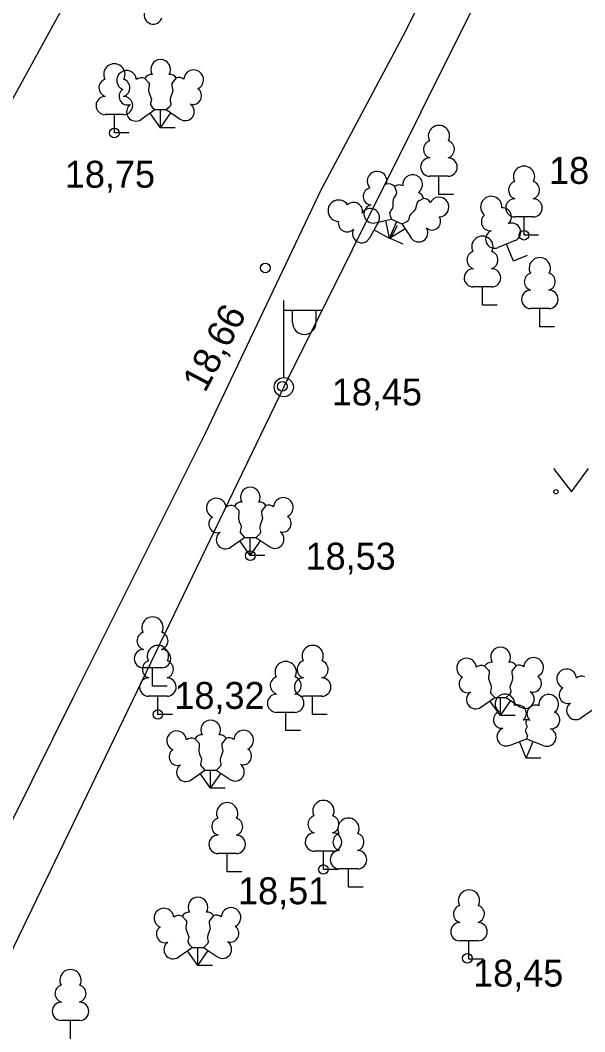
# Model space of a CAD drawing. Extents: x 713540 to 713867, y 6589774 to 6590061.
# Drawn here: x 713822.63 to 713837.3, y 6589948.37 to 6589974.67 of the extents above; entities that cross this region are included whole.
import ezdxf

# ---------------------------------------------------------------- set-up
doc = ezdxf.new("R2010")
doc.units = 0
for name, color, linetype in [('HALJASTUS', 7, 'Continuous'), ('HOONE', 7, 'Continuous'), ('KORGUS', 7, 'Continuous'), ('MPKAABEL', 7, 'Continuous'), ('POST', 7, 'Continuous'), ('PUU', 7, 'Continuous'), ('TEE', 7, 'Continuous')]:
    doc.layers.add(name, color=color, linetype=linetype)

msp = doc.modelspace()

# ---------------------------------------------------------------- linework, layer by layer
at = {"layer": 'HALJASTUS'}
for p, q in [((713836.487, 6589963.017), (713836.95, 6589962.41)), ((713836.95, 6589962.41), (713837.396, 6589963.017))]:
    msp.add_line(p, q, dxfattribs=at)
msp.add_circle((713836.549, 6589962.41), 0.055, dxfattribs=at)
at = {"layer": 'HOONE'}
msp.add_lwpolyline([(713853.13, 6590055.49), (713847.71, 6590042.61), (713840.88, 6590026.99), (713847.68, 6590019.43), (713836.38, 6589998.1), (713820.11, 6589968.4), (713812.16, 6589957.32), (713804.57, 6589946.51), (713791.35, 6589928.27), (713785.88, 6589931.15), (713778.18, 6589915.27), (713769.3, 6589896.72), (713774.33, 6589893.89), (713767.85, 6589880.54), (713761.86, 6589868.49), (713755.914, 6589856.728), (713753.12, 6589851.2), (713744.71, 6589834.75), (713742.63, 6589834)], dxfattribs=at)
at = {"layer": 'KORGUS'}
for centre in [(713825.08, 6589971.74), (713835.72, 6589969.08), (713829, 6589968.23), (713829.44, 6589965.15), (713828.61, 6589960.75), (713826.21, 6589956.62), (713830.51, 6589952.59), (713834.25, 6589950.28)]:
    msp.add_circle(centre, 0.125, dxfattribs=at)
at = {"layer": 'MPKAABEL'}
for points in [[(713829.48, 6589965.13), (713838.39, 6589983.02), (713840.65, 6589986.91), (713847.76, 6589994.21), (713849.32, 6589995.33)], [(713808.21, 6589921.82), (713821.27, 6589948.12), (713829.48, 6589965.13)]]:
    msp.add_lwpolyline(points, dxfattribs=at)
at = {"layer": 'POST'}
for p, q in [((713829.48, 6589965.38), (713829.48, 6589967.38)), ((713829.48, 6589967.13), (713830.48, 6589967.13)), ((713829.707, 6589966.809), (713829.707, 6589967.13)), ((713830.319, 6589966.809), (713830.319, 6589967.13))]:
    msp.add_line(p, q, dxfattribs=at)
msp.add_circle((713829.48, 6589965.13), 0.25, dxfattribs=at)
msp.add_arc((713830.013, 6589966.809), 0.306, 180, 0, dxfattribs=at)
at = {"layer": 'PUU'}
for p, q in [((713825.77, 6589972.09), (713826.13, 6589972.345)), ((713826.28, 6589971.87), (713826.005, 6589972.255)), ((713826.13, 6589972.345), (713826.425, 6589972.345)), ((713826.28, 6589971.87), (713826.28, 6589972.345)), ((713826.28, 6589971.87), (713826.55, 6589972.26)), ((713826.425, 6589972.345), (713826.785, 6589972.1)), ((713825.32, 6589972.215), (713824.84, 6589972.215)), ((713825.08, 6589971.74), (713825.08, 6589972.215)), ((713825.46, 6589971.74), (713825.08, 6589971.74)), ((713826.66, 6589971.87), (713826.28, 6589971.87)), ((713833.75, 6589970.615), (713833.27, 6589970.615)), ((713833.51, 6589970.14), (713833.51, 6589970.615)), ((713833.89, 6589970.14), (713833.51, 6589970.14)), ((713831.938, 6589969.428), (713831.708, 6589969.007)), ((713831.847, 6589969.402), (713832.278, 6589969.496)), ((713832.23, 6589969), (713832.128, 6589969.462)), ((713832.23, 6589969), (713832.416, 6589969.437)), ((713832.278, 6589969.496), (713832.55, 6589969.38)), ((713832.55, 6589969.38), (713832.785, 6589969.013)), ((713835.96, 6589969.555), (713835.48, 6589969.555)), ((713835.72, 6589969.08), (713835.72, 6589969.555)), ((713832.24, 6589968.99), (713831.823, 6589969.217)), ((713832.23, 6589969), (713832.631, 6589969.253)), ((713832.422, 6589969.324), (713832.24, 6589968.99)), ((713832.58, 6589968.851), (713832.23, 6589969)), ((713835.491, 6589968.941), (713835.047, 6589968.757)), ((713835.45, 6589968.41), (713835.269, 6589968.849)), ((713836.1, 6589969.08), (713835.72, 6589969.08)), ((713835.801, 6589968.555), (713835.45, 6589968.41)), ((713834.88, 6589967.735), (713834.4, 6589967.735)), ((713834.64, 6589967.26), (713834.64, 6589967.735)), ((713835.02, 6589967.26), (713834.64, 6589967.26)), ((713836.37, 6589967.175), (713835.89, 6589967.175)), ((713836.13, 6589966.7), (713836.13, 6589967.175)), ((713836.51, 6589966.7), (713836.13, 6589966.7)), ((713828.1, 6589960.97), (713828.46, 6589961.225)), ((713828.46, 6589961.225), (713828.755, 6589961.225)), ((713828.61, 6589960.75), (713828.61, 6589961.225)), ((713828.755, 6589961.225), (713829.115, 6589960.98)), ((713828.61, 6589960.75), (713828.335, 6589961.135)), ((713828.61, 6589960.75), (713828.88, 6589961.14)), ((713828.99, 6589960.75), (713828.61, 6589960.75)), ((713826.31, 6589957.835), (713825.83, 6589957.835)), ((713826.07, 6589957.36), (713826.07, 6589957.835)), ((713826.45, 6589957.36), (713826.07, 6589957.36)), ((713826.45, 6589957.095), (713825.97, 6589957.095)), ((713826.21, 6589956.62), (713826.21, 6589957.095)), ((713830.47, 6589957.095), (713829.99, 6589957.095)), ((713830.23, 6589956.62), (713830.23, 6589957.095)), ((713834.6, 6589956.81), (713834.96, 6589957.065)), ((713834.96, 6589957.065), (713835.255, 6589957.065)), ((713835.11, 6589956.59), (713835.11, 6589957.065)), ((713835.255, 6589957.065), (713835.615, 6589956.82)), ((713835.11, 6589956.59), (713834.835, 6589956.975)), ((713835.11, 6589956.59), (713835.38, 6589956.98)), ((713837.2, 6589956.53), (713837.56, 6589956.785)), ((713826.59, 6589956.62), (713826.21, 6589956.62)), ((713829.77, 6589956.675), (713829.29, 6589956.675)), ((713829.53, 6589956.2), (713829.53, 6589956.675)), ((713830.61, 6589956.62), (713830.23, 6589956.62)), ((713835.49, 6589956.59), (713835.11, 6589956.59)), ((713829.91, 6589956.2), (713829.53, 6589956.2)), ((713835.34, 6589955.815), (713835.785, 6589955.99)), ((713835.785, 6589955.99), (713836.225, 6589955.81)), ((713835.78, 6589955.48), (713835.605, 6589955.92)), ((713835.78, 6589955.48), (713835.96, 6589955.92)), ((713836.16, 6589955.48), (713835.78, 6589955.48)), ((713827.07, 6589954.92), (713827.43, 6589955.175)), ((713827.43, 6589955.175), (713827.725, 6589955.175)), ((713827.58, 6589954.7), (713827.58, 6589955.175)), ((713827.725, 6589955.175), (713828.085, 6589954.93)), ((713827.58, 6589954.7), (713827.305, 6589955.085)), ((713827.58, 6589954.7), (713827.85, 6589955.09)), ((713827.96, 6589954.7), (713827.58, 6589954.7)), ((713830.75, 6589953.065), (713830.27, 6589953.065)), ((713830.51, 6589952.59), (713830.51, 6589953.065)), ((713828.25, 6589953.005), (713827.77, 6589953.005)), ((713828.01, 6589952.53), (713828.01, 6589953.005)), ((713828.39, 6589952.53), (713828.01, 6589952.53)), ((713830.89, 6589952.59), (713830.51, 6589952.59)), ((713831.4, 6589952.605), (713830.92, 6589952.605)), ((713831.16, 6589952.13), (713831.16, 6589952.605)), ((713831.54, 6589952.13), (713831.16, 6589952.13)), ((713834.53, 6589950.735), (713834.05, 6589950.735)), ((713834.29, 6589950.26), (713834.29, 6589950.735)), ((713826.74, 6589950.31), (713827.1, 6589950.565)), ((713827.25, 6589950.09), (713826.975, 6589950.475)), ((713827.1, 6589950.565), (713827.395, 6589950.565)), ((713827.25, 6589950.09), (713827.25, 6589950.565)), ((713827.25, 6589950.09), (713827.52, 6589950.48)), ((713827.395, 6589950.565), (713827.755, 6589950.32)), ((713834.67, 6589950.26), (713834.29, 6589950.26)), ((713827.63, 6589950.09), (713827.25, 6589950.09)), ((713824.18, 6589948.665), (713823.7, 6589948.665)), ((713823.94, 6589948.19), (713823.94, 6589948.665))]:
    msp.add_line(p, q, dxfattribs=at)
for points in [[(713825.867, 6589973.157), (713825.97, 6589973.055), (713825.985, 6589973.025), (713825.985, 6589972.97), (713825.97, 6589972.88), (713825.97, 6589972.835), (713825.99, 6589972.755), (713826.03, 6589972.665), (713826.04, 6589972.62), (713826.035, 6589972.575), (713826.02, 6589972.51), (713826.02, 6589972.48), (713826.04, 6589972.44), (713826.065, 6589972.41), (713826.13, 6589972.345)], [(713826.684, 6589973.171), (713826.59, 6589973.055), (713826.575, 6589973.025), (713826.575, 6589972.97), (713826.59, 6589972.88), (713826.595, 6589972.835), (713826.575, 6589972.755), (713826.535, 6589972.665), (713826.525, 6589972.62), (713826.53, 6589972.575), (713826.545, 6589972.51), (713826.545, 6589972.48), (713826.525, 6589972.44), (713826.5, 6589972.41), (713826.43, 6589972.345)], [(713832.356, 6589970.346), (713832.41, 6589970.212), (713832.412, 6589970.178), (713832.39, 6589970.128), (713832.341, 6589970.051), (713832.324, 6589970.009), (713832.311, 6589969.928), (713832.312, 6589969.829), (713832.304, 6589969.784), (713832.281, 6589969.745), (713832.242, 6589969.691), (713832.23, 6589969.663), (713832.233, 6589969.618), (713832.244, 6589969.581), (713832.278, 6589969.496)], [(713833.112, 6589970.039), (713832.98, 6589969.968), (713832.955, 6589969.947), (713832.933, 6589969.896), (713832.911, 6589969.807), (713832.898, 6589969.764), (713832.849, 6589969.698), (713832.776, 6589969.631), (713832.75, 6589969.594), (713832.737, 6589969.55), (713832.725, 6589969.485), (713832.713, 6589969.457), (713832.679, 6589969.428), (713832.644, 6589969.41), (713832.554, 6589969.378)], [(713828.197, 6589962.037), (713828.3, 6589961.935), (713828.315, 6589961.905), (713828.315, 6589961.85), (713828.3, 6589961.76), (713828.3, 6589961.715), (713828.32, 6589961.635), (713828.36, 6589961.545), (713828.37, 6589961.5), (713828.365, 6589961.455), (713828.35, 6589961.39), (713828.35, 6589961.36), (713828.37, 6589961.32), (713828.395, 6589961.29), (713828.46, 6589961.225)], [(713829.014, 6589962.051), (713828.92, 6589961.935), (713828.905, 6589961.905), (713828.905, 6589961.85), (713828.92, 6589961.76), (713828.925, 6589961.715), (713828.905, 6589961.635), (713828.865, 6589961.545), (713828.855, 6589961.5), (713828.86, 6589961.455), (713828.875, 6589961.39), (713828.875, 6589961.36), (713828.855, 6589961.32), (713828.83, 6589961.29), (713828.76, 6589961.225)], [(713834.697, 6589957.877), (713834.8, 6589957.775), (713834.815, 6589957.745), (713834.815, 6589957.69), (713834.8, 6589957.6), (713834.8, 6589957.555), (713834.82, 6589957.475), (713834.86, 6589957.385), (713834.87, 6589957.34), (713834.865, 6589957.295), (713834.85, 6589957.23), (713834.85, 6589957.2), (713834.87, 6589957.16), (713834.895, 6589957.13), (713834.96, 6589957.065)], [(713835.514, 6589957.891), (713835.42, 6589957.775), (713835.405, 6589957.745), (713835.405, 6589957.69), (713835.42, 6589957.6), (713835.425, 6589957.555), (713835.405, 6589957.475), (713835.365, 6589957.385), (713835.355, 6589957.34), (713835.36, 6589957.295), (713835.375, 6589957.23), (713835.375, 6589957.2), (713835.355, 6589957.16), (713835.33, 6589957.13), (713835.26, 6589957.065)], [(713835.785, 6589956.485), (713835.765, 6589956.41), (713835.765, 6589956.39), (713835.775, 6589956.36), (713835.795, 6589956.325), (713835.8, 6589956.305), (713835.785, 6589956.27), (713835.76, 6589956.22), (713835.755, 6589956.195), (713835.76, 6589956.18), (713835.77, 6589956.15), (713835.805, 6589956.09), (713835.81, 6589956.07), (713835.805, 6589956.05), (713835.79, 6589956.015), (713835.785, 6589955.99)], [(713827.167, 6589955.987), (713827.27, 6589955.885), (713827.285, 6589955.855), (713827.285, 6589955.8), (713827.27, 6589955.71), (713827.27, 6589955.665), (713827.29, 6589955.585), (713827.33, 6589955.495), (713827.34, 6589955.45), (713827.335, 6589955.405), (713827.32, 6589955.34), (713827.32, 6589955.31), (713827.34, 6589955.27), (713827.365, 6589955.24), (713827.43, 6589955.175)], [(713827.984, 6589956.001), (713827.89, 6589955.885), (713827.875, 6589955.855), (713827.875, 6589955.8), (713827.89, 6589955.71), (713827.895, 6589955.665), (713827.875, 6589955.585), (713827.835, 6589955.495), (713827.825, 6589955.45), (713827.83, 6589955.405), (713827.845, 6589955.34), (713827.845, 6589955.31), (713827.825, 6589955.27), (713827.8, 6589955.24), (713827.73, 6589955.175)], [(713826.837, 6589951.377), (713826.94, 6589951.275), (713826.955, 6589951.245), (713826.955, 6589951.19), (713826.94, 6589951.1), (713826.94, 6589951.055), (713826.96, 6589950.975), (713827, 6589950.885), (713827.01, 6589950.84), (713827.005, 6589950.795), (713826.99, 6589950.73), (713826.99, 6589950.7), (713827.01, 6589950.66), (713827.035, 6589950.63), (713827.1, 6589950.565)], [(713827.654, 6589951.391), (713827.56, 6589951.275), (713827.545, 6589951.245), (713827.545, 6589951.19), (713827.56, 6589951.1), (713827.565, 6589951.055), (713827.545, 6589950.975), (713827.505, 6589950.885), (713827.495, 6589950.84), (713827.5, 6589950.795), (713827.515, 6589950.73), (713827.515, 6589950.7), (713827.495, 6589950.66), (713827.47, 6589950.63), (713827.4, 6589950.565)]]:
    msp.add_lwpolyline(points, dxfattribs=at)
for centre, radius, start, end in [((713826.089, 6589974.806), 0.238, 162.6156, 342.0093), ((713826.28, 6589973.39), 0.256, 90.0013, 211.0159), ((713826.28, 6589973.39), 0.256, 328.9841, 89.9987), ((713825.08, 6589973.26), 0.277, 332.5799, 207.4201), ((713825.397, 6589973.107), 0.256, 125.5389, 246.5536), ((713825.397, 6589973.107), 0.256, 4.5218, 125.5364), ((713827.14, 6589973.123), 0.256, 55.522, 176.5367), ((713827.14, 6589973.123), 0.256, 294.5049, 55.5195), ((713824.91, 6589972.913), 0.233, 109.0217, 253.1415), ((713825.25, 6589972.913), 0.233, 286.8508, 70.9859), ((713825.783, 6589972.974), 0.202, 65.2382, 130.7412), ((713826.042, 6589973.058), 0.202, 84.7965, 150.2995), ((713826.517, 6589973.058), 0.202, 34.3857, 95.2035), ((713826.756, 6589972.983), 0.202, 50.3173, 111.1351), ((713825.425, 6589972.69), 0.224, 125.4667, 288.5349), ((713827.12, 6589972.705), 0.224, 252.5235, 55.5918), ((713824.843, 6589972.452), 0.238, 90.0016, 269.3953), ((713825.317, 6589972.452), 0.238, 270.6047, 89.9984), ((713825.634, 6589972.284), 0.237, 125.5377, 305.5366), ((713826.918, 6589972.296), 0.237, 235.5219, 55.5208), ((713833.51, 6589971.66), 0.277, 332.5799, 207.4201), ((713833.34, 6589971.313), 0.233, 109.0217, 253.1415), ((713833.68, 6589971.313), 0.233, 286.8508, 70.9859), ((713833.273, 6589970.852), 0.238, 90.0016, 269.3953), ((713833.747, 6589970.852), 0.238, 270.6047, 89.9984), ((713831.903, 6589970.484), 0.256, 102.436, 223.4506), ((713831.903, 6589970.484), 0.256, 341.4189, 102.4335), ((713835.72, 6589970.6), 0.277, 332.5799, 207.4201), ((713832.206, 6589970.211), 0.202, 42.1353, 107.6383), ((713832.826, 6589970.398), 0.256, 66.8983, 187.9129), ((713832.826, 6589970.398), 0.256, 305.8812, 66.8958), ((713835.55, 6589970.253), 0.233, 109.0217, 253.1415), ((713835.89, 6589970.253), 0.233, 286.8508, 70.9859), ((713831.765, 6589970.09), 0.224, 102.3637, 265.432), ((713832.478, 6589970.185), 0.202, 61.6935, 127.1965), ((713832.914, 6589969.999), 0.202, 11.2827, 72.1006), ((713830.906, 6589969.718), 0.277, 33.9683, 268.8085), ((713831.292, 6589969.701), 0.233, 348.2392, 132.3743), ((713833.105, 6589969.837), 0.202, 27.2143, 88.0322), ((713833.513, 6589969.815), 0.256, 32.4191, 153.4337), ((713833.513, 6589969.815), 0.256, 271.402, 32.4166), ((713834.87, 6589969.815), 0.277, 355.0105, 229.8507), ((713835.483, 6589969.792), 0.238, 90.0016, 269.3953), ((713835.957, 6589969.792), 0.238, 270.6047, 89.9984), ((713831.728, 6589969.54), 0.238, 331.9931, 151.3868), ((713831.798, 6589969.634), 0.237, 102.4347, 282.4337), ((713835.16, 6589969.559), 0.233, 309.2815, 93.4165), ((713831.129, 6589969.402), 0.233, 170.4102, 314.53), ((713833.33, 6589969.439), 0.224, 229.4206, 32.4889), ((713834.845, 6589969.429), 0.233, 131.4524, 275.5722), ((713835.398, 6589969.159), 0.238, 293.0353, 112.429), ((713831.501, 6589969.123), 0.238, 151.39, 330.7837), ((713832.984, 6589969.141), 0.237, 212.4189, 32.4178), ((713834.959, 6589968.978), 0.238, 112.4322, 291.8259), ((713834.64, 6589968.78), 0.277, 332.5799, 207.4201), ((713834.47, 6589968.433), 0.233, 109.0217, 253.1415), ((713834.81, 6589968.433), 0.233, 286.8508, 70.9859), ((713836.13, 6589968.22), 0.277, 332.5799, 207.4201), ((713834.403, 6589967.972), 0.238, 90.0016, 269.3953), ((713834.877, 6589967.972), 0.238, 270.6047, 89.9984), ((713835.96, 6589967.873), 0.233, 109.0217, 253.1415), ((713836.3, 6589967.873), 0.233, 286.8508, 70.9859), ((713835.893, 6589967.412), 0.238, 90.0016, 269.3953), ((713836.367, 6589967.412), 0.238, 270.6047, 89.9984), ((713828.61, 6589962.27), 0.256, 90.0013, 211.0159), ((713828.61, 6589962.27), 0.256, 328.9841, 89.9987), ((713829.47, 6589962.003), 0.256, 55.522, 176.5367), ((713827.727, 6589961.987), 0.256, 125.5389, 246.5536), ((713827.727, 6589961.987), 0.256, 4.5218, 125.5364), ((713828.113, 6589961.854), 0.202, 65.2382, 130.7412), ((713828.373, 6589961.938), 0.202, 84.7965, 150.2995), ((713828.848, 6589961.938), 0.202, 34.3857, 95.2035), ((713829.086, 6589961.863), 0.202, 50.3173, 111.1351), ((713829.47, 6589962.003), 0.256, 294.5049, 55.5195), ((713827.755, 6589961.57), 0.224, 125.4667, 288.5349), ((713829.45, 6589961.585), 0.224, 252.5235, 55.5918), ((713827.964, 6589961.164), 0.237, 125.5377, 305.5366), ((713829.248, 6589961.176), 0.237, 235.5219, 55.5208), ((713826.07, 6589958.88), 0.277, 332.5799, 207.4201), ((713825.9, 6589958.533), 0.233, 109.0217, 253.1415), ((713826.24, 6589958.533), 0.233, 286.8508, 70.9859), ((713825.833, 6589958.072), 0.238, 90.0016, 269.3953), ((713826.21, 6589958.14), 0.277, 332.5799, 207.4201), ((713826.307, 6589958.072), 0.238, 270.6047, 89.9984), ((713830.23, 6589958.14), 0.277, 332.5799, 207.4201), ((713835.11, 6589958.11), 0.256, 90.0013, 211.0159), ((713835.11, 6589958.11), 0.256, 328.9841, 89.9987), ((713834.227, 6589957.827), 0.256, 4.5218, 125.5364), ((713835.97, 6589957.843), 0.256, 55.522, 176.5367), ((713835.97, 6589957.843), 0.256, 294.5049, 55.5195), ((713826.04, 6589957.793), 0.233, 109.0217, 253.1415), ((713826.38, 6589957.793), 0.233, 286.8508, 70.9859), ((713829.53, 6589957.72), 0.277, 332.5799, 207.4201), ((713830.06, 6589957.793), 0.233, 109.0217, 253.1415), ((713830.4, 6589957.793), 0.233, 286.8508, 70.9859), ((713834.227, 6589957.827), 0.256, 125.5389, 246.5536), ((713834.613, 6589957.694), 0.202, 65.2382, 130.7412), ((713834.873, 6589957.777), 0.202, 84.7965, 150.2995), ((713835.348, 6589957.777), 0.202, 34.3857, 95.2035), ((713835.586, 6589957.703), 0.202, 50.3173, 111.1351), ((713836.827, 6589957.547), 0.256, 4.5218, 125.5364), ((713825.973, 6589957.332), 0.238, 90.0016, 269.3953), ((713826.447, 6589957.332), 0.238, 270.6047, 89.9984), ((713829.36, 6589957.373), 0.233, 109.0217, 253.1415), ((713829.993, 6589957.332), 0.238, 90.0016, 269.3953), ((713829.7, 6589957.373), 0.233, 286.8508, 70.9859), ((713830.467, 6589957.332), 0.238, 270.6047, 89.9984), ((713834.255, 6589957.41), 0.224, 125.4667, 288.5349), ((713835.95, 6589957.425), 0.224, 252.5235, 55.5918), ((713836.827, 6589957.547), 0.256, 125.5389, 246.5536), ((713837.213, 6589957.414), 0.202, 65.2382, 130.7412), ((713836.855, 6589957.13), 0.224, 125.4667, 288.5349), ((713829.293, 6589956.912), 0.238, 90.0016, 269.3953), ((713829.767, 6589956.912), 0.238, 270.6047, 89.9984), ((713834.464, 6589957.004), 0.237, 125.5377, 305.5366), ((713835.223, 6589956.894), 0.256, 111.5027, 232.5173), ((713835.223, 6589956.894), 0.256, 350.4856, 111.5002), ((713835.748, 6589957.016), 0.237, 235.5219, 55.5208), ((713836.359, 6589956.885), 0.256, 67.6168, 188.6314), ((713836.359, 6589956.885), 0.256, 306.5997, 67.6143), ((713835.558, 6589956.644), 0.224, 308.5041, 111.5725), ((713836.021, 6589956.639), 0.225, 67.7016, 230.5126), ((713837.064, 6589956.724), 0.237, 125.5377, 305.5366), ((713827.58, 6589956.22), 0.256, 90.0013, 211.0159), ((713827.58, 6589956.22), 0.256, 328.9841, 89.9987), ((713835.149, 6589956.483), 0.224, 111.4304, 274.4987), ((713835.784, 6589956.247), 0.237, 66.7655, 111.5015), ((713836.426, 6589956.473), 0.224, 264.6183, 67.6866), ((713828.44, 6589955.953), 0.256, 55.522, 176.5367), ((713835.254, 6589956.038), 0.237, 111.5014, 291.5004), ((713836.315, 6589956.03), 0.237, 247.6166, 67.6155), ((713826.697, 6589955.937), 0.256, 125.5389, 246.5536), ((713826.697, 6589955.937), 0.256, 4.5218, 125.5364), ((713827.083, 6589955.804), 0.202, 65.2382, 130.7412), ((713827.343, 6589955.888), 0.202, 84.7965, 150.2995), ((713827.818, 6589955.888), 0.202, 34.3857, 95.2035), ((713828.056, 6589955.813), 0.202, 50.3173, 111.1351), ((713828.44, 6589955.953), 0.256, 294.5049, 55.5195), ((713826.725, 6589955.52), 0.224, 125.4667, 288.5349), ((713828.42, 6589955.535), 0.224, 252.5235, 55.5918), ((713826.934, 6589955.114), 0.237, 125.5377, 305.5366), ((713828.218, 6589955.126), 0.237, 235.5219, 55.5208), ((713830.51, 6589954.11), 0.277, 332.5799, 207.4201), ((713828.01, 6589954.05), 0.277, 332.5799, 207.4201), ((713827.84, 6589953.703), 0.233, 109.0217, 253.1415), ((713828.18, 6589953.703), 0.233, 286.8508, 70.9859), ((713830.34, 6589953.763), 0.233, 109.0217, 253.1415), ((713830.68, 6589953.763), 0.233, 286.8508, 70.9859), ((713831.16, 6589953.65), 0.277, 332.5799, 207.4201), ((713827.773, 6589953.242), 0.238, 90.0016, 269.3953), ((713828.247, 6589953.242), 0.238, 270.6047, 89.9984), ((713830.273, 6589953.302), 0.238, 90.0016, 269.3953), ((713830.747, 6589953.302), 0.238, 270.6047, 89.9984), ((713830.99, 6589953.303), 0.233, 109.0217, 253.1415), ((713831.33, 6589953.303), 0.233, 286.8508, 70.9859), ((713830.923, 6589952.842), 0.238, 90.0016, 269.3953), ((713831.397, 6589952.842), 0.238, 270.6047, 89.9984), ((713834.29, 6589951.78), 0.277, 332.5799, 207.4201), ((713827.25, 6589951.61), 0.256, 90.0013, 211.0159), ((713827.25, 6589951.61), 0.256, 328.9841, 89.9987), ((713826.367, 6589951.327), 0.256, 125.5389, 246.5536), ((713826.367, 6589951.327), 0.256, 4.5218, 125.5364), ((713827.013, 6589951.277), 0.202, 84.7965, 150.2995), ((713827.488, 6589951.277), 0.202, 34.3857, 95.2035), ((713828.11, 6589951.343), 0.256, 55.522, 176.5367), ((713828.11, 6589951.343), 0.256, 294.5049, 55.5195), ((713834.12, 6589951.433), 0.233, 109.0217, 253.1415), ((713834.46, 6589951.433), 0.233, 286.8508, 70.9859), ((713826.753, 6589951.194), 0.202, 65.2382, 130.7412), ((713827.726, 6589951.203), 0.202, 50.3173, 111.1351), ((713834.053, 6589950.972), 0.238, 90.0016, 269.3953), ((713834.527, 6589950.972), 0.238, 270.6047, 89.9984), ((713826.395, 6589950.91), 0.224, 125.4667, 288.5349), ((713828.09, 6589950.925), 0.224, 252.5235, 55.5918), ((713826.604, 6589950.504), 0.237, 125.5377, 305.5366), ((713827.888, 6589950.516), 0.237, 235.5219, 55.5208), ((713823.94, 6589949.71), 0.277, 332.5799, 207.4201), ((713823.77, 6589949.363), 0.233, 109.0217, 253.1415), ((713824.11, 6589949.363), 0.233, 286.8508, 70.9859), ((713823.703, 6589948.902), 0.238, 90.0016, 269.3953), ((713824.177, 6589948.902), 0.238, 270.6047, 89.9984)]:
    msp.add_arc(centre, radius, start, end, dxfattribs=at)
at = {"layer": 'TEE'}
msp.add_lwpolyline([(713815.93, 6589940.77), (713824.03, 6589957.09), (713827.45, 6589963.93), (713830.46, 6589970.28), (713832.64, 6589974.38), (713839.88, 6589989.01), (713841.08, 6589990.62), (713843.27, 6589993.16), (713845.38, 6589995.42), (713849.26, 6589999.36), (713853.21, 6590002.79), (713857.03, 6590005.94), (713860.48, 6590008.86), (713861.98, 6590009.43), (713864.03, 6590009.89), (713866.671, 6590010.167)], dxfattribs=at)

# ---------------------------------------------------------------- texts
at = {"layer": 'KORGUS'}
for s, p in [('18,75', (713823.793, 6589970.315)), ('18,49', (713836.371, 6589970.415)), ('18,45', (713830.728, 6589964.655)), ('18,53', (713830.046, 6589960.385)), ('18,32', (713826.638, 6589956.765)), ('18,51', (713828.292, 6589951.685)), ('18,45', (713834.398, 6589949.545))]:
    msp.add_text(s, height=0.7, dxfattribs=at).set_placement(p)
msp.add_text('18,66', height=0.7, rotation=62.3064, dxfattribs=at).set_placement((713827.436, 6589964.964))

doc.saveas('drawing.dxf')
